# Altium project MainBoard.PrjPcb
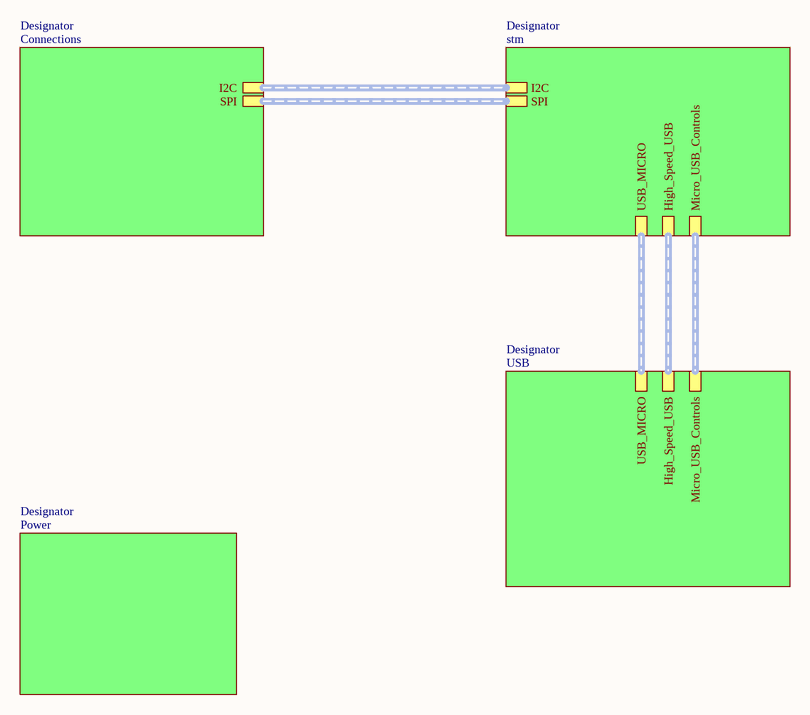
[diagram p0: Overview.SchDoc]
5 sheets, 72 parts. Net scope: hierarchical (ports join the sheet entries above them; power ports are global).
Board file: MainBoard_Rev1.PcbDoc
Sheets:
  Overview.SchDoc
    Designator = Connections.SchDoc
    Designator = stm.SchDoc
    Designator = USB.SchDoc
    Designator = Power.SchDoc

## Sheet Overview.SchDoc
size A

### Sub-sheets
Designator = Connections: I2C, SPI
Designator = stm: I2C, SPI, USB_MICRO, High_Speed_USB, Micro_USB_Controls
Designator = USB: USB_MICRO, High_Speed_USB, Micro_USB_Controls
Designator = Power: no entries

## Sheet Connections.SchDoc
size A
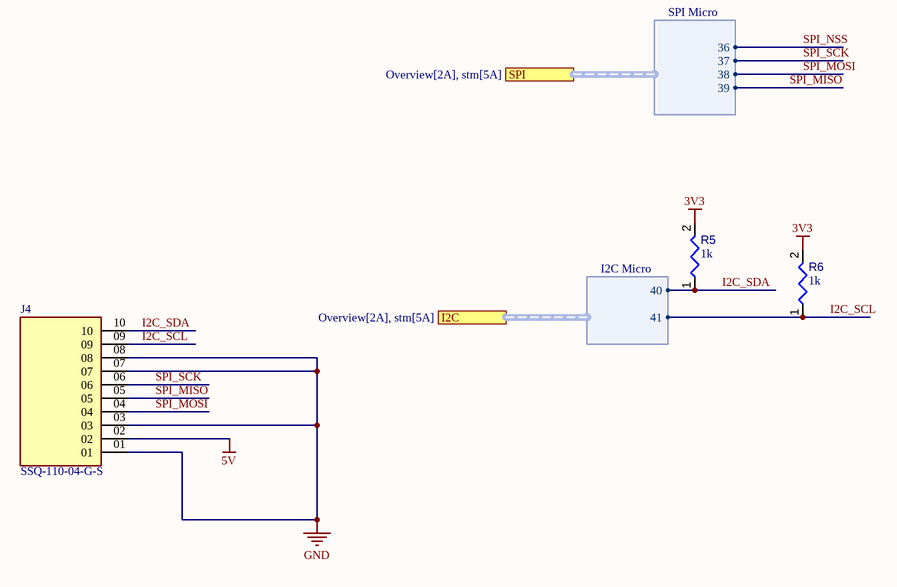
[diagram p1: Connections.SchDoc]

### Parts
J4  SSQ-110-04-G-S  [SAMTEC_SSQ-110-04-G-S]
R5  value 1k  [RESC0402(1005)_L]  (hidden comment: Resistor 1K +/-5 % 0402 63 mW)
R6  value 1k  [RESC0402(1005)_L]  (hidden comment: Resistor 1K +/-5 % 0402 63 mW)

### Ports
I2C (harness I2C Micro, see Overview[2A], stm[5A]), SPI (harness SPI Micro, see Overview[2A], stm[5A])

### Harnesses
SPI Micro: 36, 37, 39, 38
I2C Micro: 40, 41

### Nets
3V3: R5.2 R6.2
5V: J4.02
GND: J4.01 J4.03 J4.07 J4.08
I2C_SCL: J4.09 R6.1 ; port I2C.41
I2C_SDA: J4.10 R5.1 ; port I2C.40
SPI_MISO: J4.05 ; port SPI.39
SPI_MOSI: J4.04 ; port SPI.38
SPI_SCK: J4.06 ; port SPI.37

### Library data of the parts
J4 = CMP-039-000000-3: Samtec Connector .1" pitch, long ahh pins
R5 R6 = CMP-009-00157-3: Chip Resistor, 1 kOhms, +/-5 %, 63 mW, -55 to 155 degC, 0402; Tolerance: 5%; Power: 63mW

## Sheet stm.SchDoc
size B
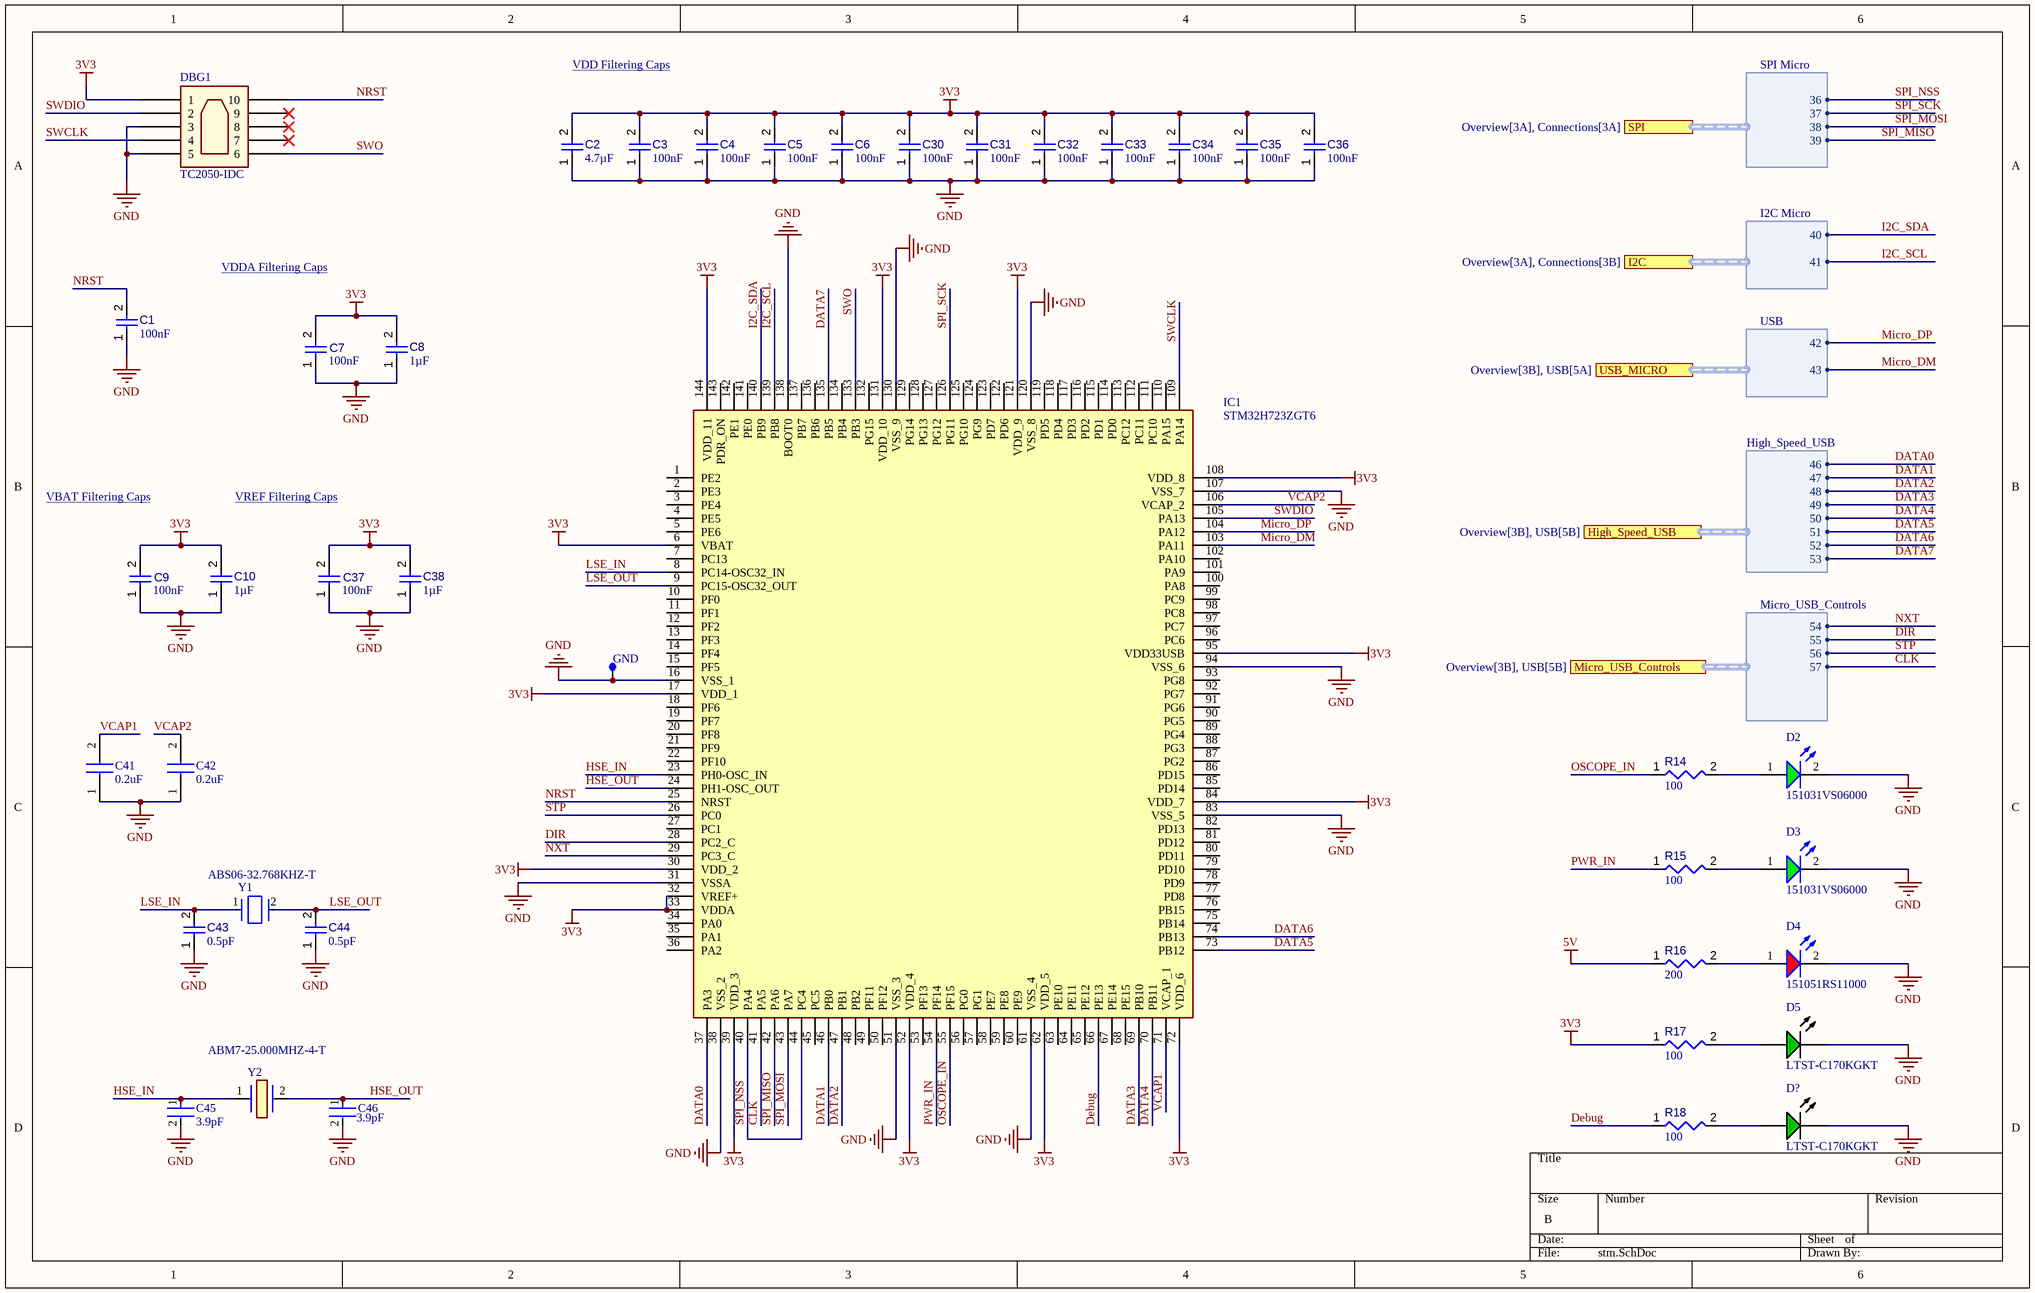
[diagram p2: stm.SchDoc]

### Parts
C1  value 100nF  [CAPC1005X56X25LL10T15]  (hidden comment: Capacitor 0.1 uF +/- 5% 16 V 0402)
C2  value 4.7µF  [CAPC0603(1608)100_L]  (hidden comment: Capacitor 4.7µF +/-20% 10V 0603)
C3  value 100nF  [CAPC0402(1005)60_L]  (hidden comment: Capacitor 100nF +/-20% 10V 0402)
C4  value 100nF  [CAPC0402(1005)60_L]  (hidden comment: Capacitor 100nF +/-20% 10V 0402)
C5  value 100nF  [CAPC0402(1005)60_L]  (hidden comment: Capacitor 100nF +/-20% 10V 0402)
C6  value 100nF  [CAPC0402(1005)60_L]  (hidden comment: Capacitor 100nF +/-20% 10V 0402)
C7  value 100nF  [CAPC0402(1005)60_L]  (hidden comment: Capacitor 100nF +/-20% 10V 0402)
C8  value 1µF  [CAPC1608X90X35ML15T15]  (hidden comment: Capacitor 1uF +/- 10% 16V 0603)
C9  value 100nF  [CAPC0402(1005)60_L]  (hidden comment: Capacitor 100nF +/-20% 10V 0402)
C10  value 1µF  [CAPC1608X90X35ML15T15]  (hidden comment: Capacitor 1uF +/- 10% 16V 0603)
C30  value 100nF  [CAPC0402(1005)60_L]  (hidden comment: Capacitor 100nF +/-20% 10V 0402)
C31  value 100nF  [CAPC0402(1005)60_L]  (hidden comment: Capacitor 100nF +/-20% 10V 0402)
C32  value 100nF  [CAPC0402(1005)60_L]  (hidden comment: Capacitor 100nF +/-20% 10V 0402)
C33  value 100nF  [CAPC0402(1005)60_L]  (hidden comment: Capacitor 100nF +/-20% 10V 0402)
C34  value 100nF  [CAPC0402(1005)60_L]  (hidden comment: Capacitor 100nF +/-20% 10V 0402)
C35  value 100nF  [CAPC0402(1005)60_L]  (hidden comment: Capacitor 100nF +/-20% 10V 0402)
C36  value 100nF  [CAPC0402(1005)60_L]  (hidden comment: Capacitor 100nF +/-20% 10V 0402)
C37  value 100nF  [CAPC0402(1005)60_L]  (hidden comment: Capacitor 100nF +/-20% 10V 0402)
C38  value 1µF  [CAPC1608X90X35ML15T15]  (hidden comment: Capacitor 1uF +/- 10% 16V 0603)
C41  0.2uF  [CAPC3216X94N]
C42  0.2uF  [CAPC3216X94N]
C43  value 0.5pF  [CAPC1005X56X25ML10T15]  (hidden comment: Capacitor 0.5 pF +/- 0.1pF 25 V 0402)
C44  value 0.5pF  [CAPC1005X56X25ML10T15]  (hidden comment: Capacitor 0.5 pF +/- 0.1pF 25 V 0402)
C45  3.9pF  [FP-GJM155-0_05-IPC_C]
C46  3.9pF  [FP-GJM155-0_05-IPC_C]
D2  151031VS06000  [WL-TMRC_D3.95H5.3]
D3  151031VS06000  [WL-TMRC_D3.95H5.3]
D4  151051RS11000  [WL-TMRC_D5.9H8.7]
D5  LTST-C170KGKT  [LTST-LTST-C170KGKT-2_V]
D?  LTST-C170KGKT  [LTST-LTST-C170KGKT-2_V]
DBG1  TC2050-IDC  [TC2050-IDC-Footprint-1]
GND  TESTPAD  [TESTPAD-Footprint-1]  (value not drawn)
IC1  STM32H723ZGT6  [QFP50P2200X2200X160-144N]
R14  value 100  [RESC0402(1005)_L]  (hidden comment: 100R2F)
R15  value 100  [RESC0402(1005)_L]  (hidden comment: 100R2F)
R16  value 200  [RESC0402(1005)_L]  (hidden comment: 200R2J)
R17  value 100  [RESC0402(1005)_L]  (hidden comment: 100R2F)
R18  value 100  [RESC0402(1005)_L]  (hidden comment: 100R2F)
Y1  ABS06-32.768KHZ-T  [FP-ABS06-MFG]
Y2  ABM7-25.000MHZ-4-T  [ABM7]

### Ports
High_Speed_USB (harness High_Speed_USB, see Overview[3B], USB[5B]), I2C (harness I2C Micro, see Overview[3A], Connections[3B]), Micro_USB_Controls (harness Micro_USB_Controls, see Overview[3B], USB[5B]), SPI (harness SPI Micro, see Overview[3A], Connections[3A]), USB_MICRO (harness USB, see Overview[3B], USB[5A])

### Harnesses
SPI Micro: 36, 37, 39, 38
I2C Micro: 40, 41
USB: 42, 43
High_Speed_USB: 46, 47, 48, 49, 50, 51, 52, 53
Micro_USB_Controls: 54, 55, 56, 57

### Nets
3V3: C2.2 C3.2 C4.2 C5.2 C6.2 C7.2 C8.2 C9.2 C10.2 C30.2 C31.2 C32.2 C33.2 C34.2 C35.2 C36.2 C37.2 C38.2 DBG1.1 IC1.6(VBAT) IC1.17(VDD_1) IC1.30(VDD_2) IC1.32(VREF+) IC1.33(VDDA) IC1.39(VDD_3) IC1.52(VDD_4) IC1.62(VDD_5) IC1.72(VDD_6) IC1.84(VDD_7) IC1.95(VDD33USB) IC1.108(VDD_8) IC1.121(VDD_9) IC1.131(VDD_10) IC1.144(VDD_11) R17.1
5V: R16.1
GND: C1.1 C2.1 C3.1 C4.1 C5.1 C6.1 C7.1 C8.1 C9.1 C10.1 C30.1 C31.1 C32.1 C33.1 C34.1 C35.1 C36.1 C37.1 C38.1 C41.1(C1) C42.1(C1) C43.1 C44.1 C45.2 C46.2 D2.2(K) D3.2(K) D4.2(K) D5.1(K) D?.1(K) DBG1.3 DBG1.5 GND.PAD IC1.16(VSS_1) IC1.31(VSSA) IC1.38(VSS_2) IC1.51(VSS_3) IC1.61(VSS_4) IC1.83(VSS_5) IC1.94(VSS_6) IC1.107(VSS_7) IC1.120(VSS_8) IC1.130(VSS_9) IC1.138(BOOT0)
CLK: IC1.41(PA5) ; port Micro_USB_Controls.57
DATA0: IC1.37(PA3) ; port High_Speed_USB.46
DATA1: IC1.46(PB0) ; port High_Speed_USB.47
DATA2: IC1.47(PB1) ; port High_Speed_USB.48
DATA3: IC1.69(PB10) ; port High_Speed_USB.49
DATA4: IC1.70(PB11) ; port High_Speed_USB.50
DATA5: IC1.73(PB12) ; port High_Speed_USB.51
DATA6: IC1.74(PB13) ; port High_Speed_USB.52
DATA7: IC1.135(PB5) ; port High_Speed_USB.53
Debug: IC1.66(PE13) R18.1
DIR: IC1.28(PC2_C) ; port Micro_USB_Controls.55
HSE_IN: C45.1 IC1.23(PH0-OSC_IN) Y2.1
HSE_OUT: C46.1 IC1.24(PH1-OSC_OUT) Y2.2
I2C_SCL: IC1.139(PB8) ; port I2C.41
I2C_SDA: IC1.140(PB9) ; port I2C.40
LSE_IN: C43.2 IC1.8(PC14-OSC32_IN) Y1.1
LSE_OUT: C44.2 IC1.9(PC15-OSC32_OUT) Y1.2
Micro_DM: IC1.103(PA11) ; port USB_MICRO.43
Micro_DP: IC1.104(PA12) ; port USB_MICRO.42
NRST: C1.2 DBG1.10 IC1.25(NRST)
NXT: IC1.29(PC3_C) ; port Micro_USB_Controls.54
OSCOPE_IN: IC1.55(PF15) R14.1
PWR_IN: IC1.54(PF14) R15.1
SPI_MISO: IC1.42(PA6) ; port SPI.39
SPI_MOSI: IC1.43(PA7) ; port SPI.38
SPI_NSS: IC1.40(PA4) IC1.44(PC4) ; port SPI.36
SPI_SCK: IC1.126(PG11) ; port SPI.37
STP: IC1.26(PC0) ; port Micro_USB_Controls.56
SWCLK: DBG1.4 IC1.109(PA14)
SWDIO: DBG1.2 IC1.105(PA13)
SWO: DBG1.6 IC1.133(PB3)
VCAP1: C41.2(C2) IC1.71(VCAP_1)
VCAP2: C42.2(C2) IC1.106(VCAP_2)
NetD2_1: D2.1(A) R14.2
NetD3_1: D3.1(A) R15.2
NetD4_1: D4.1(A) R16.2
NetD5_2: D5.2(A) R17.2
NetD?_2: D?.2(A) R18.2

Not connected (* = marked no-connect by the designer): DBG1 7* 8* 9*; IC1 1(PE2) 2(PE3) 3(PE4) 4(PE5) 5(PE6) 7(PC13) 10(PF0) 11(PF1) 12(PF2) 13(PF3) 14(PF4) 15(PF5) 18(PF6) 19(PF7) 20(PF8) 21(PF9) 22(PF10) 27(PC1) 34(PA0) 35(PA1) 36(PA2) 45(PC5) 48(PB2) 49(PF11) 50(PF12) 53(PF13) 56(PG0) 57(PG1) 58(PE7) 59(PE8) 60(PE9) 63(PE10) 64(PE11) 65(PE12) 67(PE14) 68(PE15) 75(PB14) 76(PB15) 77(PD8) 78(PD9) 79(PD10) 80(PD11) 81(PD12) 82(PD13) 85(PD14) 86(PD15) 87(PG2) 88(PG3) 89(PG4) 90(PG5) 91(PG6) 92(PG7) 93(PG8) 96(PC6) 97(PC7) 98(PC8) 99(PC9) 100(PA8) 101(PA9) 102(PA10) 110(PA15) 111(PC10) 112(PC11) 113(PC12) 114(PD0) 115(PD1) 116(PD2) 117(PD3) 118(PD4) 119(PD5) 122(PD6) 123(PD7) 124(PG9) 125(PG10) 127(PG12) 128(PG13) 129(PG14) 132(PG15) 134(PB4) 136(PB6) 137(PB7) 141(PE0) 142(PE1) 143(PDR_ON)

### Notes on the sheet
- VDD Filtering Caps
- VDDA Filtering Caps
- VBAT Filtering Caps
- VREF Filtering Caps

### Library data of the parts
C1 = CMP-001-00001-6: Chip Capacitor, 0.1 uF, +/- 5%, 16 V, 0402 (1005 Metric); Capacitor Type: Ceramic; Voltage Rating: 16V
C2 = CMP-001-00076-4: Chip Capacitor, 4.7µF +/-20%, 10V, 0603, Thickness 1 mm; Tolerance: 10%
C3-C7 C9 C30-C37 = CMP-001-00061-3: Chip Capacitor, 100nF +/-20%, 10V, 0402, Thickness 0.6 mm; Tolerance: 20%
C8 C10 C38 = CMP-001-00004-6: Chip Capacitor, 1 uF, +/- 10%, 16 V, 0603 (1608 Metric); Capacitor Type: Ceramic
C41 C42 = 12063C204KAT4A: Capacitor; Manufacturer_Name: Kyocera AVX
C43 C44 = CMP-001-00002-6: Chip Capacitor, 0.5 pF, +/- 0.1pF, 25 V, 0402 (1005 Metric); Voltage Rating: 25V; Tolerance: 20%; Capacitor Type: Ceramic
C45 C46 = CMP-2008-03853-2: Multi-Layer Ceramic Capacitor 3.9pF C0G  ±0.25pF 0402 Paper T/R; Voltage Rating (DC): 50V
D2 D3 = CMP-1488-00004-2: NexarPartId: 29717805; Peak Wavelength: 560nm; Lens Style: Circular, Diffused, Round; Forward Voltage: 2.2V; Lens Size: 3mm; Wavelength: 568nm; Test Current: 20mA; Max Reverse Voltage (DC): 5V; Color: Green; Forward Current: 100mA; Viewing Angle: 60°; Luminous Intensity: 30mcd
D4 = CMP-007-00039-1: WL-TMRC Red Color Diffused 5 mm Round Through Hole LED; Forward Voltage: 2.1V; Forward Current: 100mA
D5 D? = CMP-2000-06620-1: Ultra Bright AlInGaP Chip LED, 75 mW, -55 to 85 degC, 2-Pin SMD (0805), RoHS, Tape and Reel; Manufacturer: Lite-On; Forward Current: 30mA; Power Dissipation Max: 75mW; Emitting Color: YellowGreen; Type: Uni-Color; Forward Voltage: 2.4V; Dominant Wave Length: 571nm; Test Current (It): 20mA; Product Length (mm): 2mm; Peak Wavelength: 574nm; Power Dissipation: 75W; Product Depth (mm): 1.25mm; DELETED: Compliant; High Brightness: Yes; Product Height (mm): 1.1mm; Luminous Intensity: 35mcd; Shape Type: Rectangular; Chip Material: AlGaInP; Viewing Angle: 130deg; Number of  Elements: 1; Reverse Voltage: 5V; Rad Hardened: No
DBG1 = CMP-002-00071-4: CBL PLUG-OF-NAILS 10-PIN W/LEGS
GND = CMP-002-00073-1: PCB TESTPAD
IC1 = STM32H723ZGT6: Integrated Circuit; Manufacturer_Name: STMicroelectronics
R14 R15 R17 R18 = CMP-009-00065-2: 100R 0.063W 1% 0402 (1005 Metric)  SMD; Power: 63mW
R16 = CMP-009-00079-2: 200R 0.063W 5% 0402 (1005 Metric)  SMD; Power: 63mW
Y1 = CMP-2000-05035-2: Crystal 32.768kHz ±20ppm (Tol) 12.5pF FUND 90kΩ 2-Pin Mini-CSMD T/R; Insulation Resistance: 500MR; ESR (Equivalent Series Resistance): 90kR
Y2 = ABM7-25.000MHZ-4-T: Crystal or Oscillator; Manufacturer_Name: ABRACON

## Sheet USB.SchDoc
size B
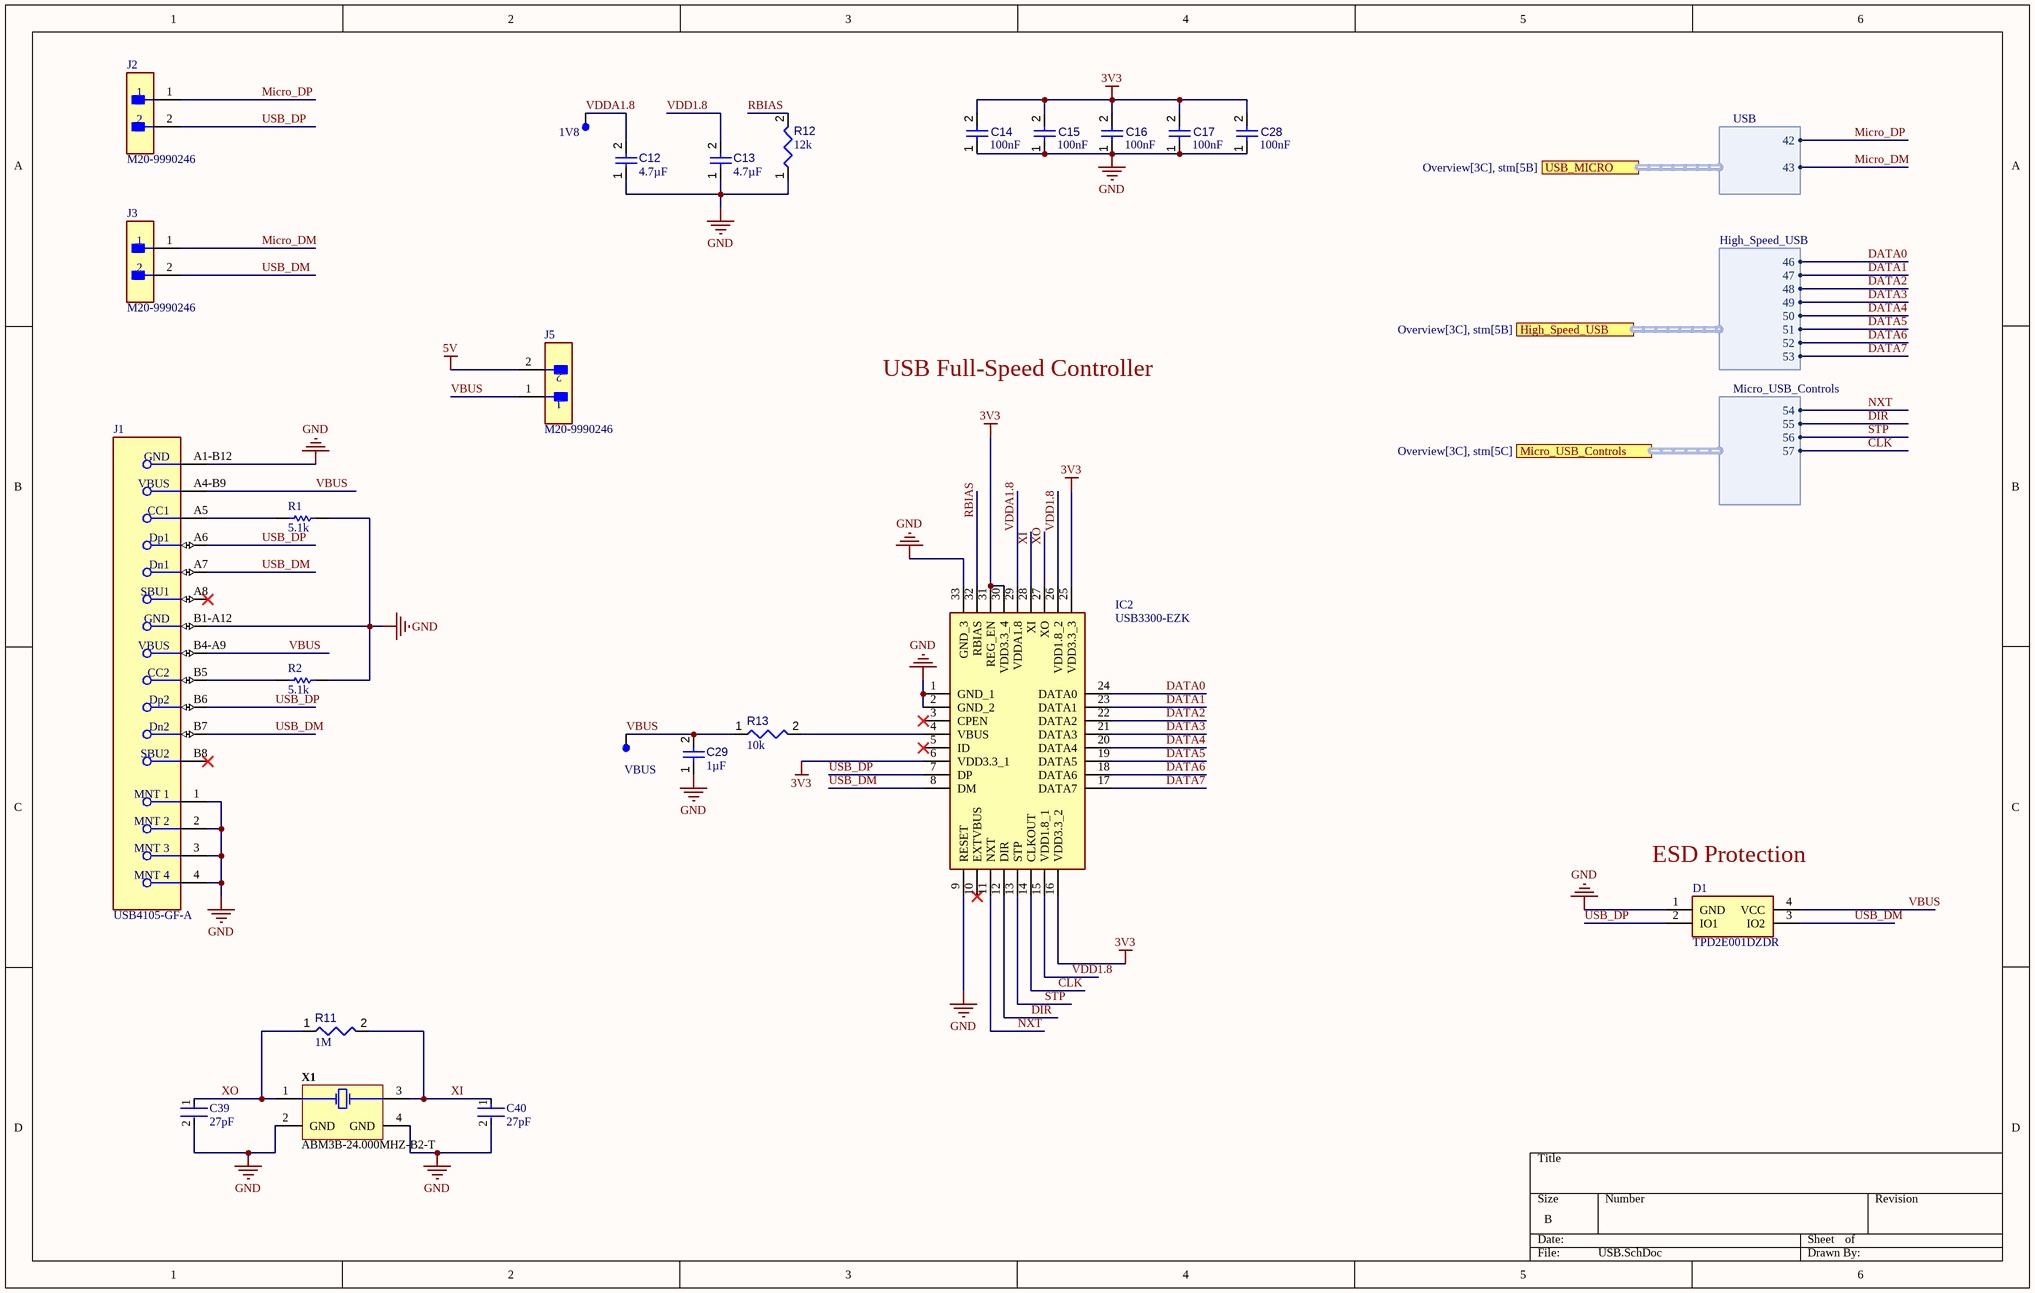
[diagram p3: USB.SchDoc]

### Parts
(Parts that share a designator on the sheet are numbered #1, #2 ... from top to bottom, then left to right.)
1V8  TESTPAD  [TESTPAD-Footprint-1]  (value not drawn)
C12  value 4.7µF  [CAPC0603(1608)100_L]  (hidden comment: Capacitor 4.7µF +/-20% 10V 0603)
C13  value 4.7µF  [CAPC0603(1608)100_L]  (hidden comment: Capacitor 4.7µF +/-20% 10V 0603)
C14  value 100nF  [CAPC0402(1005)60_L]  (hidden comment: Capacitor 100nF +/-20% 10V 0402)
C15  value 100nF  [CAPC0402(1005)60_L]  (hidden comment: Capacitor 100nF +/-20% 10V 0402)
C16  value 100nF  [CAPC0402(1005)60_L]  (hidden comment: Capacitor 100nF +/-20% 10V 0402)
C17  value 100nF  [CAPC0402(1005)60_L]  (hidden comment: Capacitor 100nF +/-20% 10V 0402)
C28  value 100nF  [CAPC0402(1005)60_L]  (hidden comment: Capacitor 100nF +/-20% 10V 0402)
C29  value 1µF  [CAPC1608X90X35ML15T15]  (hidden comment: Capacitor 1uF +/- 10% 16V 0603)
C39  27pF  [FP-GCM155-0_05-IPC_C]
C40  27pF  [FP-GCM155-0_05-IPC_C]
D1  TPD2E001DZDR  [TPD2E001DZDR]
IC2  USB3300-EZK  [QFN50P500X500X100-33N-D]
J1  USB4105-GF-A  [FP-USB4105-GF-A-MFG]
J2  M20-9990246  [FP-M20-9990246-MFG]
J3  M20-9990246  [FP-M20-9990246-MFG]
J5#1  M20-9990246  [FP-M20-9990246-MFG]
R1  5.1k  [RESC1608X55X25ML10T15]
R2  5.1k  [RESC1608X55X25ML10T15]
R11  value 1M  [RESC0402(1005)_L]  (hidden comment: Resistor 1M +/-1 % 0402 63 mW)
R12  value 12k  [RESC0402(1005)_L]  (hidden comment: 12KR2F)
R13  value 10k  [RESC0402(1005)_L]  (hidden comment: Resistor 10K  +/-1 % 0402 63 mW)
VBUS  TESTPAD  [TESTPAD-Footprint-1]  (value not drawn)
X1  ABM3B-24.000MHZ-B2-T  [ABRA-ABM3B-4_V]

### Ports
High_Speed_USB (harness High_Speed_USB, see Overview[3C], stm[5B]), Micro_USB_Controls (harness Micro_USB_Controls, see Overview[3C], stm[5C]), USB_MICRO (harness USB, see Overview[3C], stm[5B])

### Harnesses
USB: 42, 43
High_Speed_USB: 46, 47, 48, 49, 50, 51, 52, 53
Micro_USB_Controls: 54, 55, 56, 57

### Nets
3V3: C14.2 C15.2 C16.2 C17.2 C28.2 IC2.6(VDD3.3_1) IC2.16(VDD3.3_2) IC2.25(VDD3.3_3) IC2.30(VDD3.3_4) IC2.31(REG_EN)
5V: J5#1.2
GND: C12.1 C13.1 C14.1 C15.1 C16.1 C17.1 C28.1 C29.1 C39.2 C40.2 D1.1(GND) IC2.1(GND_1) IC2.2(GND_2) IC2.9(RESET) IC2.33(GND_3) J1.1(MNT_1) J1.2(MNT_2) J1.3(MNT_3) J1.4(MNT_4) J1.A1-B12(GND) J1.B1-A12(GND) R1.2 R2.2 R12.1 X1.2(GND) X1.4(GND)
CLK: IC2.14(CLKOUT) ; port Micro_USB_Controls.57
DATA0: IC2.24(DATA0) ; port High_Speed_USB.46
DATA1: IC2.23(DATA1) ; port High_Speed_USB.47
DATA2: IC2.22(DATA2) ; port High_Speed_USB.48
DATA3: IC2.21(DATA3) ; port High_Speed_USB.49
DATA4: IC2.20(DATA4) ; port High_Speed_USB.50
DATA5: IC2.19(DATA5) ; port High_Speed_USB.51
DATA6: IC2.18(DATA6) ; port High_Speed_USB.52
DATA7: IC2.17(DATA7) ; port High_Speed_USB.53
DIR: IC2.12(DIR) ; port Micro_USB_Controls.55
Micro_DM: J3.1 ; port USB_MICRO.43
Micro_DP: J2.1 ; port USB_MICRO.42
NXT: IC2.11(NXT) ; port Micro_USB_Controls.54
RBIAS: IC2.32(RBIAS) R12.2
STP: IC2.13(STP) ; port Micro_USB_Controls.56
USB_DM: D1.3(IO2) IC2.8(DM) J1.A7(Dn1) J1.B7(Dn2) J3.2
USB_DP: D1.2(IO1) IC2.7(DP) J1.A6(Dp1) J1.B6(Dp2) J2.2
VBUS: C29.2 D1.4(VCC) J1.A4-B9(VBUS) J1.B4-A9(VBUS) J5#1.1 R13.1 VBUS.PAD
VDD1.8: C13.2 IC2.15(VDD1.8_1) IC2.26(VDD1.8_2)
VDDA1.8: 1V8.PAD C12.2 IC2.29(VDDA1.8)
XI: C40.1 IC2.28(XI) R11.2 X1.3(X2)
XO: C39.1 IC2.27(XO) R11.1 X1.1(X1)
NetIC2_4: IC2.4(VBUS) R13.2
NetJ1_A5: J1.A5(CC1) R1.1
NetJ1_B5: J1.B5(CC2) R2.1

Not connected (* = marked no-connect by the designer): IC2 3(CPEN)* 5(ID)* 10(EXTVBUS)*; J1 A8(SBU1)* B8(SBU2)*

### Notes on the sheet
- USB Full-Speed Controller
- (near D1) ESD Protection

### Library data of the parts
1V8 VBUS = CMP-002-00073-1: PCB TESTPAD
C12 C13 = CMP-001-00076-4: as C2 on sheet stm
C14-C17 C28 = CMP-001-00061-3: as C3 on sheet stm
C29 = CMP-001-00004-6: as C8 on sheet stm
C39 C40 = CMP-06035-034210-1: Ceramic Capacitor for Automotive 27pF ±5% 50VDC C0G 0402 Paper T/R; Voltage Rating: 50V
D1 = TPD2E001DZDR: Diode; Manufacturer_Name: Texas Instruments
IC2 = USB3300-EZK: Integrated Circuit; Manufacturer_Name: Microchip
J1 = CMP-002-00080-1: Conn USB 2.0 Type C RCP 24 POS 0.3mm/0.5mm Solder RA SMD 24 Terminal 1 Port T/R
J2 J3 J5#1 = CMP-15831-000009-1: CONN HEADER VERT 2POS 2.54MM; Manufacturer: Harwin; Conn Gender: Male; Conn Orientation: Vertical; Number Of Contacts: 2; Current Rating: 3A
R1 R2 = CMP-2000-04091-1: Manufacturer: Yageo; Part Number: RC0603FR-075K1L
R11 = CMP-009-00165-3: Chip Resistor, 1 MOhms, +/-1 %, 63 mW, -55 to 155 degC, 0402; Tolerance: 1%; Power: 63mW
R12 = CMP-009-00071-2: 12K 0.063W 1% 0402 (1005 Metric)  SMD; Power: 63mW
R13 = CMP-009-00149-3: Chip Resistor, 10 kOhms, +/-1 %, 63 mW, -55 to 125 degC, 0402; Power: 63mW; Tolerance: 1%
X1 = CMP-003-00019-2: Ceramic SMD Crystal, 24 MHz, +/- 20 ppm, 18 pF, -20 to 70 degC, 4-Pin SMD, RoHS, Tape and Reel; Manufacturer: Abracon; Load Capacitance: 18pF; Frequency Tolerance: 20ppm; ESR: 50; Resistance: 50Ohm; Frequency: 24MHz

## Sheet Power.SchDoc
size B
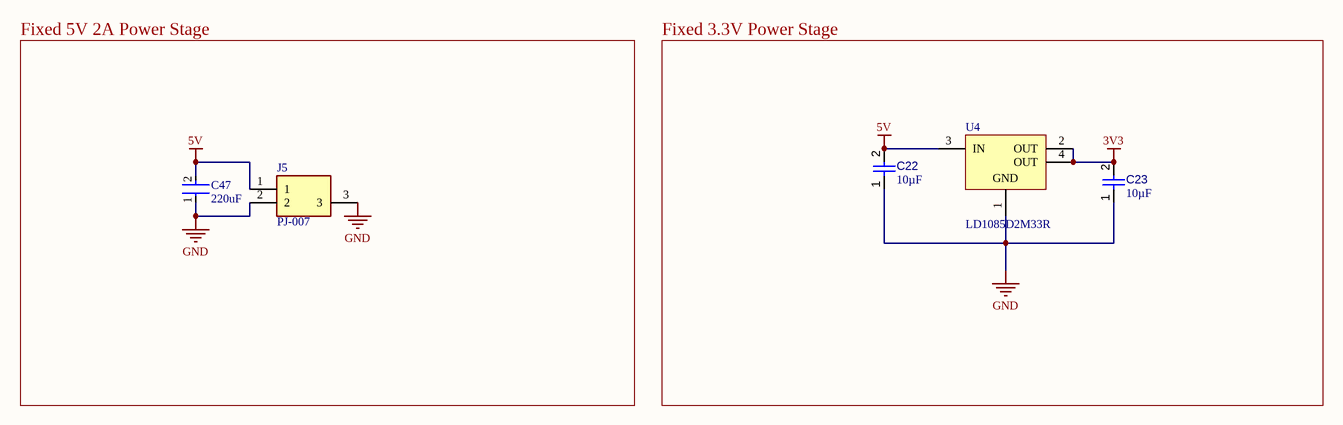
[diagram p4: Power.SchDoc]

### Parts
(Parts that share a designator on the sheet are numbered #1, #2 ... from top to bottom, then left to right.)
C22  value 10µF  [CAPC0402(1005)60_L]  (hidden comment: Capacitor 10µF +/-40% 6.3V 0402)
C23  value 10µF  [CAPC0402(1005)60_L]  (hidden comment: Capacitor 10µF +/-40% 6.3V 0402)
C47  220uF  [FP-GRM31C-0_3-e0_3_0_9-IPC_C]
J5#2  PJ-007  [PJ007]
U4  LD1085D2M33R  [D2PAK_A_L]

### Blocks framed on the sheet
Fixed 5V 2A Power Stage: C47 J5#2
Fixed 3.3V Power Stage: C22 C23 U4

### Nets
3V3: C23.2 U4.2(OUT) U4.4(OUT)
5V: C22.2 C47.2 J5#2.1 U4.3(IN)
GND: C22.1 C23.1 C47.1 J5#2.2 J5#2.3 U4.1(GND)

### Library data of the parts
C22 C23 = CMP-001-00074-3: Chip Capacitor, 10µF +/-40%, 6.3V, 0402, Thickness 0.6 mm; Tolerance: 10%
C47 = CMP-06035-000079-2: Chip Multilayer Ceramic Capacitors for General Purpose, 1206, 220uF, X5R, 15%, 20%, 6.3V
J5#2 = PJ-007: Connector; Manufacturer_Name: Same Sky
U4 = CMP-0244-00506-1: 3A, Low Drop Positive Voltage Regulator, 3.3V, 4-Pin D2PAK/A

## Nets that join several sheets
3V3: Connections (R5.2 R6.2), stm (35 pins), USB (10 pins), Power (C23.2 U4.2 U4.4)
5V: Connections (J4.02), stm (R16.1), USB (J5#1.2), Power (C22.2 C47.2 J5#2.1 U4.3)
GND: Connections (J4.01 J4.03 J4.07 J4.08), stm (44 pins), USB (26 pins), Power (6 pins)
CLK: stm (IC1.41), USB (IC2.14)
DATA0: stm (IC1.37), USB (IC2.24)
DATA1: stm (IC1.46), USB (IC2.23)
DATA2: stm (IC1.47), USB (IC2.22)
DATA3: stm (IC1.69), USB (IC2.21)
DATA4: stm (IC1.70), USB (IC2.20)
DATA5: stm (IC1.73), USB (IC2.19)
DATA6: stm (IC1.74), USB (IC2.18)
DATA7: stm (IC1.135), USB (IC2.17)
DIR: stm (IC1.28), USB (IC2.12)
I2C_SCL: Connections (J4.09 R6.1), stm (IC1.139)
I2C_SDA: Connections (J4.10 R5.1), stm (IC1.140)
Micro_DM: stm (IC1.103), USB (J3.1)
Micro_DP: stm (IC1.104), USB (J2.1)
NXT: stm (IC1.29), USB (IC2.11)
SPI_MISO: Connections (J4.05), stm (IC1.42)
SPI_MOSI: Connections (J4.04), stm (IC1.43)
SPI_SCK: Connections (J4.06), stm (IC1.126)
STP: stm (IC1.26), USB (IC2.13)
